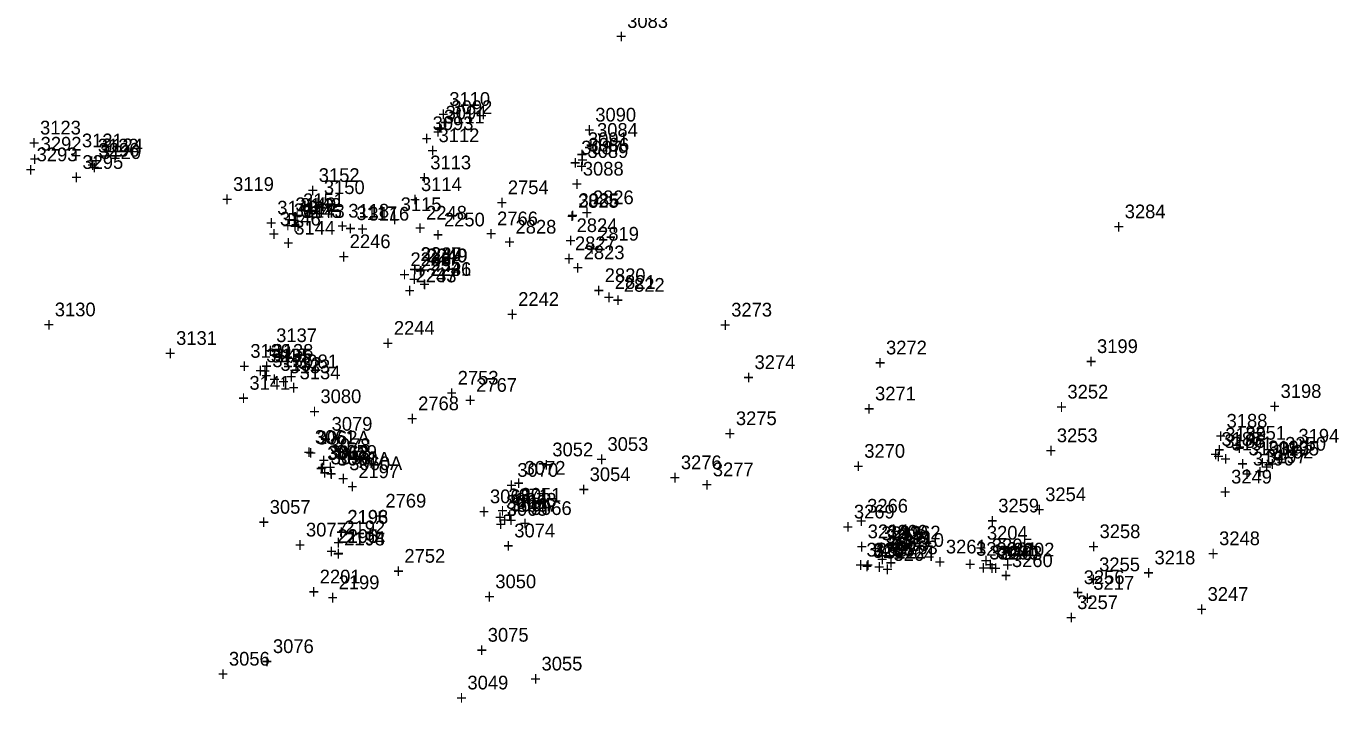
# Model space of a CAD drawing. Extents: x 1136220 to 1137808, y 528804 to 531215.
# Drawn here: x 1136987.1 to 1137226.3, y 529765.5 to 529888.8 of the extents above; entities that cross this region are included whole.
import ezdxf

# ---------------------------------------------------------------- set-up
doc = ezdxf.new("R2010")
doc.units = 0
for name, color, linetype in [('S_Buildings', 7, 'Continuous'), ('S_Drainage_CB', 7, 'Continuous'), ('S_Drainage_Culvert_Top', 7, 'Continuous'), ('S_Drainage_Invert', 7, 'Continuous'), ('S_Drainage_Sump', 7, 'Continuous'), ('S_Ground_Elevation', 7, 'Continuous'), ('S_Ground_SpotElevation', 7, 'Continuous'), ('S_Roadway_Centerline', 7, 'Continuous'), ('S_Roadway_Edge_Pavement', 7, 'Continuous'), ('S_Traffic_Sign_SinglePost', 7, 'Continuous'), ('S_Utilities_Gas_Gate', 7, 'Continuous'), ('S_Utilities_GuyWire3', 7, 'Continuous'), ('S_Utilities_Pole_Joint', 7, 'Continuous'), ('S_Utilities_Pole_StreetLight', 7, 'Continuous'), ('S_Utilities_UG_Gas_Line', 7, 'Continuous'), ('S_Utilities_UG_Sanitary_MH', 7, 'Continuous'), ('S_Utilities_UG_Water_Gate', 7, 'Continuous'), ('S_Utilities_UG_Water_Line', 7, 'Continuous'), ('S_Utilities_UG_Water_Shutoff', 7, 'Continuous')]:
    doc.layers.add(name, color=color, linetype=linetype)

msp = doc.modelspace()

# ---------------------------------------------------------------- texts
at = {"layer": 'S_Buildings'}
for s, p in [('3199', (1137182.28, 529829.22)), ('+', (1137180.22, 529826.47)), ('3198', (1137215.73, 529821.03)), ('+', (1137213.67, 529818.28)), ('3054', (1137089.82, 529805.88)), ('+', (1137087.76, 529803.13)), ('3057', (1137031.52, 529799.93)), ('+', (1137029.46, 529797.18)), ('3265', (1137141.62, 529792.13)), ('+', (1137139.56, 529789.38)), ('3257', (1137178.66, 529782.55)), ('+', (1137176.6, 529779.8)), ('3056', (1137024.08, 529772.25)), ('3055', (1137081.05, 529771.36)), ('+', (1137022.02, 529769.5)), ('+', (1137078.99, 529768.61))]:
    msp.add_text(s, height=2.5, dxfattribs=at).set_placement(p)
at = {"layer": 'S_Drainage_CB'}
for s, p in [('3092', (1137064.64, 529872.77)), ('+', (1137062.58, 529870.02)), ('3086', (1137089.59, 529865.92)), ('+', (1137087.53, 529863.17)), ('3142', (1137037.09, 529854.95)), ('3284', (1137187.33, 529853.77)), ('+', (1137035.03, 529852.2)), ('+', (1137185.27, 529851.02)), ('3135', (1137031.72, 529827.5)), ('+', (1137029.66, 529824.75)), ('3186', (1137205.49, 529811.92)), ('3192', (1137214.26, 529810)), ('3058', (1137042.62, 529808.93)), ('+', (1137203.43, 529809.17)), ('+', (1137040.56, 529806.18)), ('+', (1137212.2, 529807.25)), ('3064', (1137075.41, 529800.35)), ('+', (1137073.35, 529797.6)), ('3208', (1137143.76, 529794.59)), ('+', (1137141.69, 529791.84)), ('3200', (1137164.2, 529791.58)), ('+', (1137162.14, 529788.83))]:
    msp.add_text(s, height=2.5, dxfattribs=at).set_placement(p)
at = {"layer": 'S_Drainage_Culvert_Top'}
for s, p in [('3093', (1137061.2, 529869.85)), ('3090', (1137090.84, 529871.41)), ('+', (1137088.78, 529868.66)), ('+', (1137059.14, 529867.1)), ('3088', (1137088.58, 529861.56)), ('3150', (1137041.38, 529858.19)), ('+', (1137086.52, 529858.81)), ('3148', (1137032.89, 529854.46)), ('+', (1137039.32, 529855.44)), ('2248', (1137060.01, 529853.53)), ('+', (1137030.82, 529851.71)), ('3146', (1137033.37, 529852.45)), ('3144', (1137035.99, 529850.81)), ('2250', (1137063.27, 529852.3)), ('+', (1137031.31, 529849.7)), ('2246', (1137046.09, 529848.33)), ('+', (1137057.94, 529850.78)), ('+', (1137061.21, 529849.55)), ('+', (1137033.93, 529848.06)), ('2247', (1137058.99, 529846.01)), ('+', (1137044.03, 529845.58)), ('2245', (1137057.16, 529845.06)), ('2249', (1137060.15, 529845.76)), ('+', (1137055.1, 529842.31)), ('+', (1137056.93, 529843.26)), ('+', (1137058.09, 529843.01)), ('2243', (1137058.11, 529842.1)), ('2241', (1137060.78, 529843.3)), ('+', (1137056.05, 529839.36)), ('+', (1137058.72, 529840.55)), ('2242', (1137076.8, 529837.81)), ('+', (1137074.74, 529835.07)), ('2244', (1137054.14, 529832.54)), ('3137', (1137032.69, 529831.21)), ('+', (1137052.08, 529829.79)), ('3139', (1137027.98, 529828.35)), ('+', (1137030.63, 529828.46)), ('+', (1137025.92, 529825.6)), ('3188', (1137205.89, 529815.62)), ('3062A', (1137040.07, 529812.55)), ('+', (1137203.83, 529812.87)), ('3194', (1137218.99, 529812.9)), ('3190', (1137209.89, 529810.57)), ('+', (1137038.01, 529809.8)), ('3062', (1137041.99, 529809.72)), ('3060', (1137043.74, 529808.79)), ('3060A', (1137046, 529807.87)), ('3196', (1137210.69, 529808.72)), ('+', (1137216.93, 529810.15)), ('+', (1137039.93, 529806.97)), ('+', (1137041.68, 529806.04)), ('2197', (1137047.65, 529806.42)), ('3070', (1137076.64, 529806.66)), ('3072', (1137077.97, 529807.04)), ('+', (1137207.83, 529807.82)), ('+', (1137208.63, 529805.97)), ('+', (1137043.93, 529805.12)), ('+', (1137045.59, 529803.67)), ('+', (1137074.58, 529803.91)), ('+', (1137075.91, 529804.29)), ('3068', (1137071.65, 529801.85)), ('2196', (1137045.65, 529798.08)), ('+', (1137069.59, 529799.1)), ('3066', (1137079.11, 529799.7)), ('+', (1137077.05, 529796.95)), ('+', (1137043.59, 529795.33)), ('2200', (1137043.83, 529794.61)), ('2198', (1137045.08, 529794.15)), ('3214', (1137140.49, 529795.47)), ('3210', (1137146.94, 529793.89)), ('3204', (1137162.21, 529795.21)), ('+', (1137041.77, 529791.86)), ('+', (1137043.02, 529791.4)), ('+', (1137138.43, 529792.72)), ('3212', (1137143.67, 529791.76)), ('+', (1137160.15, 529792.46)), ('3206', (1137160.23, 529792.27)), ('3202', (1137167.07, 529792.15)), ('+', (1137141.61, 529789.01)), ('+', (1137144.88, 529791.14)), ('+', (1137158.17, 529789.52)), ('+', (1137165.01, 529789.4)), ('2201', (1137040.63, 529787.23)), ('2199', (1137044.07, 529786.18)), ('+', (1137038.57, 529784.48)), ('+', (1137042.01, 529783.43))]:
    msp.add_text(s, height=2.5, dxfattribs=at).set_placement(p)
at = {"layer": 'S_Drainage_Invert'}
for s, p in [('3094', (1137063.57, 529871.79)), ('+', (1137061.51, 529869.04)), ('3091', (1137089.5, 529866.94)), ('+', (1137087.44, 529864.19)), ('3089', (1137089.43, 529864.77)), ('+', (1137087.37, 529862.02)), ('3151', (1137037.6, 529855.82)), ('3147', (1137035.9, 529853.99)), ('3149', (1137036.19, 529855.07)), ('3145', (1137037.24, 529853.85)), ('+', (1137033.84, 529851.24)), ('+', (1137034.13, 529852.32)), ('+', (1137035.17, 529851.1)), ('+', (1137035.54, 529853.07)), ('2239', (1137059.06, 529845.97)), ('2238', (1137057.16, 529845.06)), ('2240', (1137060.04, 529845.73)), ('+', (1137055.1, 529842.31)), ('+', (1137057, 529843.22)), ('+', (1137057.98, 529842.98)), ('2237', (1137058.11, 529842.14)), ('2236', (1137060.81, 529843.27)), ('+', (1137056.05, 529839.39)), ('+', (1137058.75, 529840.52)), ('3140', (1137030.89, 529827.54)), ('3138', (1137032.03, 529828.36)), ('+', (1137028.83, 529824.79)), ('+', (1137029.96, 529825.61)), ('3061', (1137039.74, 529812.67)), ('3189', (1137205.65, 529813.11)), ('3191', (1137206.8, 529811.46)), ('3195', (1137215.31, 529810.54)), ('+', (1137037.68, 529809.92)), ('3063', (1137042.19, 529809.89)), ('3061A', (1137043.83, 529808.7)), ('+', (1137203.59, 529810.36)), ('+', (1137204.73, 529808.71)), ('3197', (1137213.05, 529809.12)), ('+', (1137040.13, 529807.14)), ('+', (1137041.77, 529805.95)), ('+', (1137210.99, 529806.37)), ('+', (1137213.24, 529807.79)), ('3069', (1137074.58, 529800.81)), ('3071', (1137075.02, 529802.01)), ('3073', (1137076.34, 529801.21)), ('2193', (1137045.68, 529798.12)), ('+', (1137072.96, 529799.26)), ('3067', (1137076.59, 529800.28)), ('+', (1137072.52, 529798.06)), ('+', (1137074.28, 529798.46)), ('+', (1137074.53, 529797.53)), ('+', (1137043.62, 529795.37)), ('2195', (1137043.85, 529794.6)), ('2194', (1137045.12, 529794.22)), ('3215', (1137142.97, 529795.11)), ('3211', (1137144.81, 529794.34)), ('+', (1137041.79, 529791.85)), ('+', (1137043.06, 529791.47)), ('+', (1137140.91, 529792.36)), ('+', (1137142.75, 529791.59)), ('3213', (1137144.23, 529793.16)), ('3207', (1137162.64, 529791.6)), ('3205', (1137163.12, 529792.91)), ('3203', (1137164.87, 529791.53)), ('+', (1137142.17, 529790.41)), ('+', (1137161.06, 529790.16)), ('+', (1137160.58, 529788.85)), ('+', (1137162.81, 529788.78))]:
    msp.add_text(s, height=2.5, dxfattribs=at).set_placement(p)
at = {"layer": 'S_Drainage_Sump'}
for s, p in [('3087', (1137088.28, 529865.42)), ('+', (1137086.22, 529862.67)), ('3143', (1137037.74, 529853.86)), ('+', (1137035.67, 529851.11)), ('3136', (1137031.99, 529826.64)), ('+', (1137029.92, 529823.89)), ('3187', (1137204.96, 529812.3)), ('3193', (1137213.47, 529810.76)), ('3059', (1137043.63, 529809.94)), ('+', (1137202.9, 529809.55)), ('+', (1137041.57, 529807.19)), ('+', (1137211.41, 529808.01)), ('3065', (1137074.71, 529799.56)), ('+', (1137072.64, 529796.81)), ('3209', (1137144.03, 529795.39)), ('+', (1137141.97, 529792.64)), ('3201', (1137163.94, 529792.21)), ('+', (1137161.88, 529789.46))]:
    msp.add_text(s, height=2.5, dxfattribs=at).set_placement(p)
at = {"layer": 'S_Ground_Elevation'}
for s, p in [('3292', (1136989.77, 529866.11)), ('3296', (1137000.32, 529865.01)), ('3124', (1137000.96, 529865.81)), ('+', (1136987.71, 529863.36)), ('3293', (1136989.04, 529864.17)), ('3295', (1136997.38, 529862.78)), ('+', (1136998.9, 529863.06)), ('+', (1136986.98, 529861.42)), ('+', (1136998.26, 529862.26)), ('+', (1136995.32, 529860.03)), ('3274', (1137119.87, 529826.3)), ('+', (1137117.81, 529823.55)), ('3271', (1137141.83, 529820.59)), ('+', (1137139.77, 529817.84)), ('3253', (1137174.96, 529812.97)), ('+', (1137172.9, 529810.22)), ('3249', (1137206.72, 529805.44)), ('+', (1137204.66, 529802.69))]:
    msp.add_text(s, height=2.5, dxfattribs=at).set_placement(p)
at = {"layer": 'S_Ground_SpotElevation'}
for s, p in [('3266', (1137140.39, 529800.13)), ('3259', (1137164.28, 529800.17)), ('+', (1137138.33, 529797.38)), ('+', (1137162.22, 529797.42)), ('3262', (1137146.33, 529795.25)), ('3258', (1137182.74, 529795.48)), ('+', (1137144.27, 529792.5)), ('3264', (1137145.18, 529791.34)), ('3263', (1137145.81, 529792.53)), ('3261', (1137154.74, 529792.69)), ('+', (1137180.68, 529792.73)), ('+', (1137143.75, 529789.78)), ('+', (1137152.68, 529789.94)), ('3260', (1137166.77, 529790.21)), ('+', (1137143.12, 529788.59)), ('+', (1137164.71, 529787.46))]:
    msp.add_text(s, height=2.5, dxfattribs=at).set_placement(p)
at = {"layer": 'S_Roadway_Centerline'}
for s, p in [('2754', (1137074.91, 529858.17)), ('+', (1137072.85, 529855.42)), ('2753', (1137065.77, 529823.46)), ('+', (1137063.7, 529820.71)), ('3275', (1137116.47, 529816.08)), ('+', (1137114.41, 529813.33)), ('3270', (1137139.86, 529810.13)), ('+', (1137137.8, 529807.38)), ('3254', (1137172.84, 529802.22)), ('+', (1137170.78, 529799.47)), ('3248', (1137204.53, 529794.2)), ('2752', (1137056.06, 529791)), ('+', (1137202.47, 529791.45)), ('+', (1137054, 529788.25))]:
    msp.add_text(s, height=2.5, dxfattribs=at).set_placement(p)
at = {"layer": 'S_Roadway_Edge_Pavement'}
for s, p in [('3083', (1137096.66, 529888.46)), ('+', (1137094.6, 529885.71)), ('3110', (1137064.24, 529874.27)), ('+', (1137062.18, 529871.52)), ('3111', (1137063.26, 529871.06)), ('+', (1137061.2, 529868.31)), ('3112', (1137062.28, 529867.65)), ('3084', (1137091.16, 529868.63)), ('+', (1137089.1, 529865.89)), ('3120', (1137000.62, 529864.58)), ('+', (1137060.22, 529864.9)), ('3113', (1137060.77, 529862.7)), ('+', (1136998.56, 529861.83)), ('3119', (1137024.84, 529858.77)), ('+', (1137058.71, 529859.95)), ('3114', (1137059.08, 529858.73)), ('+', (1137022.78, 529856.02)), ('+', (1137057.02, 529855.98)), ('2825', (1137087.68, 529855.69)), ('3085', (1137087.79, 529855.83)), ('3118', (1137045.83, 529853.9)), ('3117', (1137047.31, 529853.45)), ('3116', (1137049.49, 529853.35)), ('3115', (1137055.38, 529855.08)), ('+', (1137043.77, 529851.15)), ('+', (1137053.32, 529852.33)), ('+', (1137085.62, 529852.94)), ('+', (1137085.73, 529853.08)), ('2824', (1137087.44, 529851.26)), ('+', (1137045.25, 529850.7)), ('+', (1137047.43, 529850.6)), ('+', (1137085.37, 529848.51)), ('2823', (1137088.73, 529846.3)), ('+', (1137086.67, 529843.55)), ('2820', (1137092.57, 529842.15)), ('+', (1137090.5, 529839.4)), ('2821', (1137094.41, 529840.91)), ('2822', (1137096.05, 529840.39)), ('+', (1137092.35, 529838.16)), ('+', (1137093.99, 529837.64)), ('3130', (1136992.35, 529835.91)), ('3273', (1137115.62, 529835.87)), ('+', (1136990.29, 529833.16)), ('+', (1137113.55, 529833.12)), ('3131', (1137014.46, 529830.7)), ('+', (1137012.4, 529827.95)), ('3272', (1137143.83, 529828.97)), ('3132', (1137033.46, 529825.97)), ('3133', (1137035.11, 529825.54)), ('3134', (1137036.96, 529824.44)), ('+', (1137141.77, 529826.22)), ('+', (1137031.4, 529823.22)), ('+', (1137033.05, 529822.79)), ('+', (1137034.9, 529821.69)), ('3080', (1137040.76, 529820.09)), ('3252', (1137176.89, 529820.93)), ('+', (1137174.83, 529818.18)), ('+', (1137038.7, 529817.34)), ('3079', (1137042.79, 529815.06)), ('3251', (1137209.28, 529813.42)), ('+', (1137040.72, 529812.31)), ('3078', (1137042.45, 529811.19)), ('3052', (1137083.02, 529810.39)), ('3053', (1137093.07, 529811.38)), ('+', (1137207.22, 529810.67)), ('3250', (1137216.57, 529811.42)), ('+', (1137040.39, 529808.44)), ('+', (1137091.01, 529808.63)), ('3276', (1137106.44, 529808.05)), ('+', (1137214.51, 529808.67)), ('+', (1137080.96, 529807.64)), ('3277', (1137112.27, 529806.76)), ('+', (1137104.37, 529805.3)), ('+', (1137110.21, 529804.01)), ('3051', (1137077.23, 529802.13)), ('+', (1137075.17, 529799.38)), ('3269', (1137137.97, 529799.07)), ('3077', (1137038.12, 529795.78)), ('+', (1137135.91, 529796.32)), ('+', (1137036.06, 529793.03)), ('3268', (1137140.27, 529792.13)), ('3267', (1137141.44, 529791.89)), ('+', (1137138.21, 529789.38)), ('+', (1137139.38, 529789.14)), ('3255', (1137182.67, 529789.45)), ('3050', (1137072.63, 529786.35)), ('3256', (1137179.85, 529787.11)), ('+', (1137180.61, 529786.7)), ('+', (1137177.79, 529784.36)), ('3247', (1137202.43, 529784.05)), ('+', (1137070.57, 529783.6)), ('+', (1137200.37, 529781.3)), ('3076', (1137032.1, 529774.54)), ('+', (1137030.04, 529771.79)), ('3049', (1137067.55, 529767.91)), ('+', (1137065.49, 529765.16))]:
    msp.add_text(s, height=2.5, dxfattribs=at).set_placement(p)
at = {"layer": 'S_Traffic_Sign_SinglePost'}
for s, p in [('3122', (1137000.18, 529865.77)), ('+', (1136998.12, 529863.02))]:
    msp.add_text(s, height=2.5, dxfattribs=at).set_placement(p)
at = {"layer": 'S_Utilities_Gas_Gate'}
for s, p in [('2766', (1137072.95, 529852.5)), ('+', (1137070.89, 529849.75)), ('2767', (1137069.14, 529822.15)), ('+', (1137067.08, 529819.4))]:
    msp.add_text(s, height=2.5, dxfattribs=at).set_placement(p)
at = {"layer": 'S_Utilities_GuyWire3'}
for s, p in [('3123', (1136989.66, 529869.05)), ('+', (1136987.6, 529866.3))]:
    msp.add_text(s, height=2.5, dxfattribs=at).set_placement(p)
at = {"layer": 'S_Utilities_Pole_Joint'}
for s, p in [('3121', (1136997.29, 529866.71)), ('+', (1136995.23, 529863.96)), ('2819', (1137091.36, 529849.7)), ('+', (1137089.3, 529846.95)), ('3217', (1137181.6, 529786.08)), ('+', (1137179.54, 529783.33)), ('3075', (1137071.25, 529776.61)), ('+', (1137069.18, 529773.86))]:
    msp.add_text(s, height=2.5, dxfattribs=at).set_placement(p)
at = {"layer": 'S_Utilities_Pole_StreetLight'}
for s, p in [('2826', (1137090.41, 529856.34)), ('+', (1137088.35, 529853.59))]:
    msp.add_text(s, height=2.5, dxfattribs=at).set_placement(p)
at = {"layer": 'S_Utilities_UG_Gas_Line'}
for s, p in [('3152', (1137040.45, 529860.4)), ('+', (1137038.39, 529857.65)), ('2828', (1137076.31, 529850.98)), ('+', (1137074.25, 529848.23)), ('2827', (1137087.14, 529847.96)), ('+', (1137085.08, 529845.21)), ('3218', (1137192.76, 529790.7)), ('+', (1137190.7, 529787.95))]:
    msp.add_text(s, height=2.5, dxfattribs=at).set_placement(p)
at = {"layer": 'S_Utilities_UG_Sanitary_MH'}
for s, p in [('2235', (1137058.94, 529844.2)), ('+', (1137056.88, 529841.45)), ('2192', (1137045.12, 529796.19)), ('+', (1137043.06, 529793.44))]:
    msp.add_text(s, height=2.5, dxfattribs=at).set_placement(p)
at = {"layer": 'S_Utilities_UG_Water_Gate'}
for s, p in [('3081', (1137036.51, 529826.44)), ('+', (1137034.45, 529823.69))]:
    msp.add_text(s, height=2.5, dxfattribs=at).set_placement(p)
at = {"layer": 'S_Utilities_UG_Water_Line'}
for s, p in [('2768', (1137058.56, 529818.79)), ('+', (1137056.5, 529816.04)), ('2769', (1137052.6, 529801.05)), ('+', (1137050.54, 529798.3))]:
    msp.add_text(s, height=2.5, dxfattribs=at).set_placement(p)
at = {"layer": 'S_Utilities_UG_Water_Shutoff'}
for s, p in [('3141', (1137027.82, 529822.53)), ('+', (1137025.76, 529819.78)), ('3074', (1137076.08, 529795.62)), ('+', (1137074.02, 529792.87))]:
    msp.add_text(s, height=2.5, dxfattribs=at).set_placement(p)

doc.saveas('drawing.dxf')
